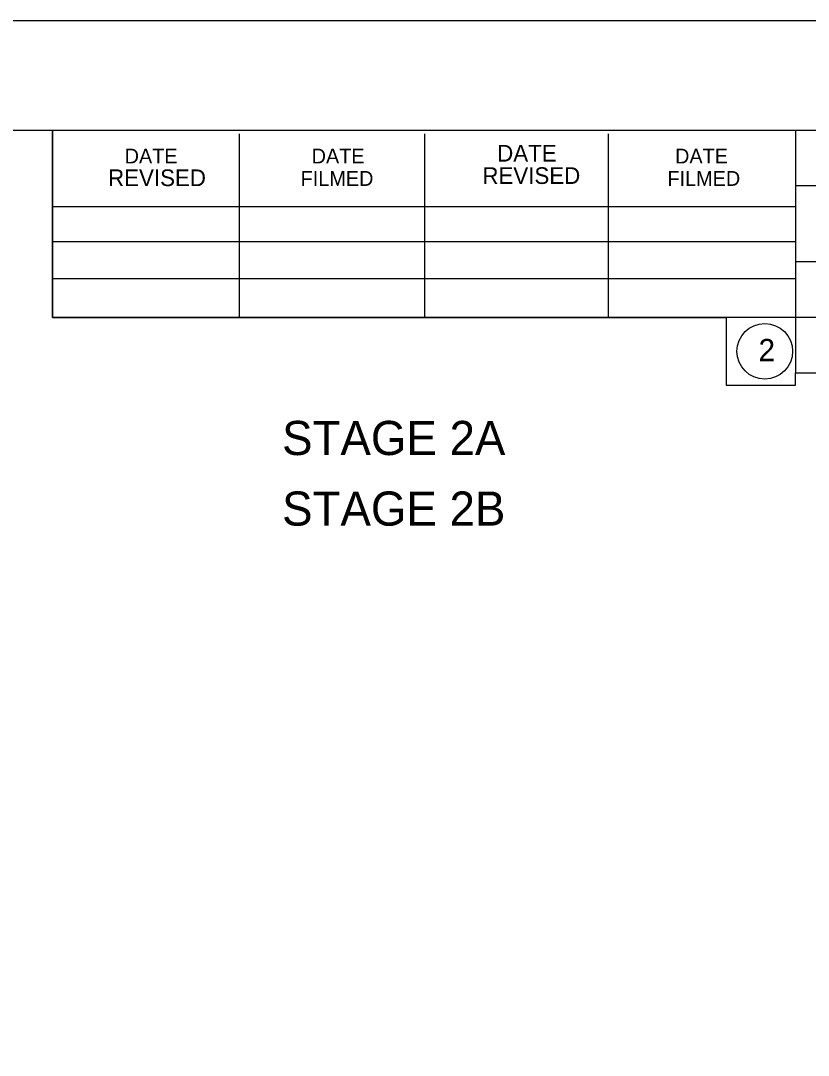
# Model space of a CAD drawing. Extents: x 0 to 1228740, y 0 to 152440.
# Drawn here: x 25.03 to 29.18, y 16.55 to 22 of the extents above; entities that cross this region are included whole.
import ezdxf

# ---------------------------------------------------------------- set-up
doc = ezdxf.new("R2010")
doc.units = 0
for name, color, linetype in [('R_Border', 7, 'Continuous'), ('R_No Plot', 7, 'Continuous'), ('R_XS_EARTHWORK_STAGE2', 7, 'Continuous')]:
    doc.layers.add(name, color=color, linetype=linetype)

msp = doc.modelspace()

# ---------------------------------------------------------------- linework, layer by layer
at = {"layer": 'R_Border'}
for p, q in [((1.516, 21.4232), (33.4231, 21.4232)), ((25.1971, 20.4352), (25.1971, 21.4232)), ((26.1831, 20.4352), (26.1831, 21.4032)), ((27.1591, 20.4352), (27.1591, 21.4032)), ((28.1271, 20.4352), (28.1271, 21.4032)), ((29.1131, 21.4232), (29.1131, 20.1432)), ((33.4231, 21.1292), (29.1131, 21.1292)), ((25.1971, 21.0212), (29.1131, 21.0212)), ((25.1971, 20.8352), (29.1131, 20.8352)), ((33.4231, 20.7292), (29.1131, 20.7292)), ((25.1971, 20.4352), (25.1971, 20.6412)), ((25.1971, 20.6412), (29.1131, 20.6412)), ((33.4231, 20.4352), (25.1971, 20.4352)), ((29.1131, 20.1432), (33.4231, 20.1432))]:
    msp.add_line(p, q, dxfattribs=at)
msp.add_lwpolyline([(34, 22), (0, 22), (0, 0), (34, 0)], close=True, dxfattribs=at)
msp.add_circle((28.9518, 20.2569), 0.1467, dxfattribs=at)
at = {"layer": 'R_No Plot'}
for points in [[(33.4231, 17.4052), (33.4231, 10.8708), (1.516, 10.8708), (1.516, 21.4232), (25.1971, 21.4232), (25.1971, 20.4352), (28.7491, 20.4352), (28.7491, 20.0782), (29.1131, 20.0782), (29.1131, 20.1432), (30.6665, 20.1432)], [(33.4231, 17.4052), (33.4231, 0.6568), (1.516, 0.6568), (1.516, 21.4232), (25.1971, 21.4232), (25.1971, 20.4352), (28.7491, 20.4352), (28.7491, 20.0782), (29.1131, 20.0782), (29.1131, 20.1432), (30.6665, 20.1432)]]:
    msp.add_lwpolyline(points, dxfattribs=at)

# ---------------------------------------------------------------- texts
at = {"layer": 'R_Border'}
for s, height, p in [('DATE', 0.08792, (27.5409, 21.2572)), ('DATE', 0.07819, (25.5769, 21.2472)), ('DATE', 0.07819, (26.5629, 21.2472)), ('DATE', 0.07819, (28.4789, 21.2472)), ('REVISED', 0.08792, (27.4629, 21.1392)), ('REVISED', 0.08792, (25.4893, 21.1279)), ('FILMED', 0.07819, (26.5049, 21.1292)), ('FILMED', 0.07819, (28.4389, 21.1292)), ('2', 0.1172, (28.9189, 20.2049))]:
    msp.add_text(s, height=height, dxfattribs=at).set_placement(p)
at = {"layer": 'R_XS_EARTHWORK_STAGE2'}
for s, p in [('STAGE 2A', (26.407, 19.71)), ('STAGE 2B', (26.407, 19.3378))]:
    msp.add_text(s, height=0.18, dxfattribs=at).set_placement(p)

doc.saveas('drawing.dxf')
